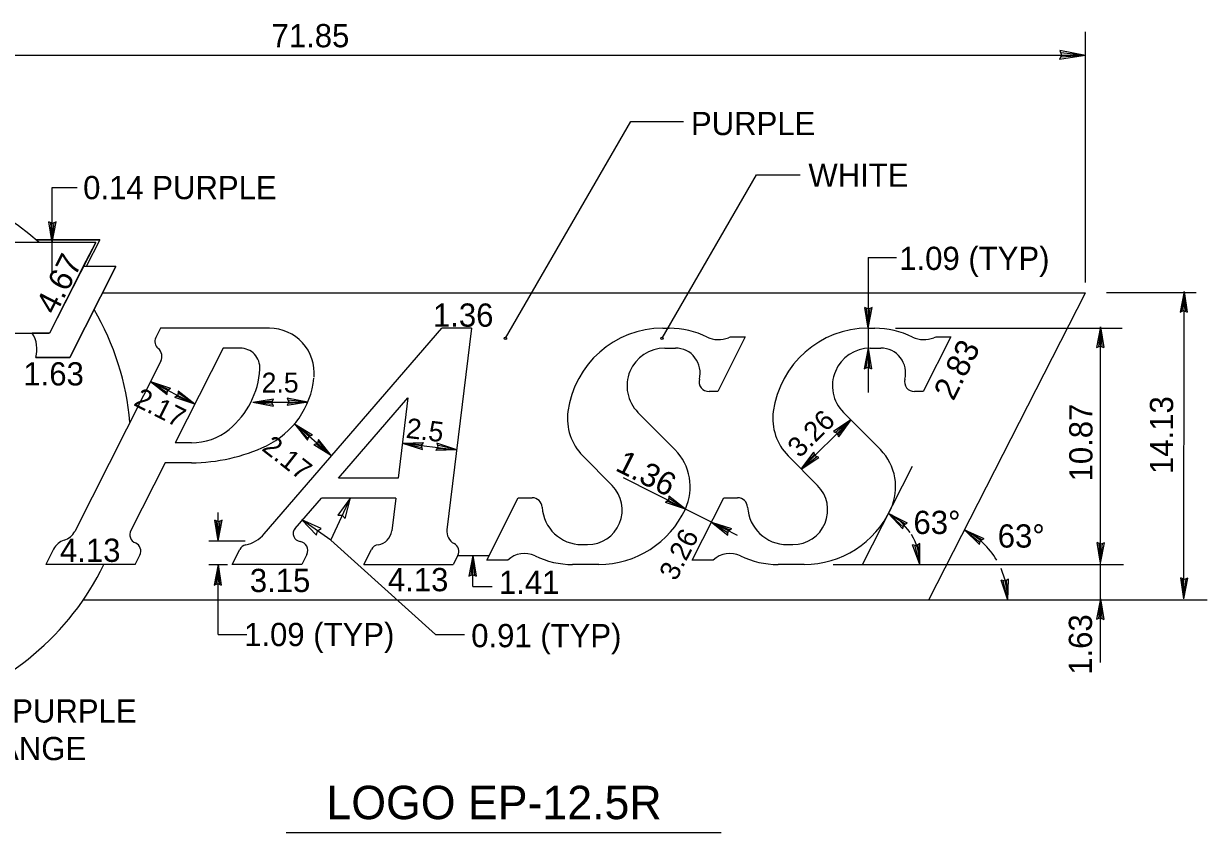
# Model space of a CAD drawing. Extents: x 10268197 to 10268826, y 2141503 to 2142677.
# Drawn here: x 10268696.97 to 10268727.52, y 2142400.42 to 2142421.3 of the extents above; entities that cross this region are included whole.
import ezdxf

# ---------------------------------------------------------------- set-up
doc = ezdxf.new("R2010")
doc.units = 0
doc.layers.add('Default', color=7, linetype='Continuous')
doc.layers.add('TextDetails', color=7, linetype='Continuous')

msp = doc.modelspace()

# ---------------------------------------------------------------- linework, layer by layer
at = {"layer": 'Default'}
for p, q in [((10268724.378, 2142414.961), (10268724.378, 2142421.09)), ((10268724.378, 2142420.48), (10268684.064, 2142420.48)), ((10268723.763, 2142420.49), (10268723.71, 2142420.374)), ((10268724.378, 2142420.48), (10268723.71, 2142420.374)), ((10268724.378, 2142420.48), (10268723.714, 2142420.609)), ((10268723.714, 2142420.609), (10268723.763, 2142420.49)), ((10268724.378, 2142420.48), (10268723.738, 2142420.435)), ((10268724.378, 2142420.48), (10268723.739, 2142420.547)), ((10268709.405, 2142413.178), (10268712.638, 2142418.777)), ((10268712.638, 2142418.777), (10268713.999, 2142418.777)), ((10268713.448, 2142413.178), (10268715.883, 2142417.397)), ((10268715.883, 2142417.397), (10268717.013, 2142417.397)), ((10268697.702, 2142415.718), (10268697.702, 2142417.074)), ((10268697.702, 2142417.074), (10268698.344, 2142417.074)), ((10268697.702, 2142415.653), (10268697.617, 2142416.188)), ((10268697.71, 2142416.145), (10268697.617, 2142416.188)), ((10268697.702, 2142415.653), (10268697.666, 2142416.165)), ((10268697.702, 2142415.653), (10268697.805, 2142416.184)), ((10268697.702, 2142415.653), (10268697.755, 2142416.164)), ((10268697.805, 2142416.184), (10268697.71, 2142416.145)), ((10268698.825, 2142415.653), (10268691.433, 2142415.653)), ((10268698.931, 2142415.719), (10268697.287, 2142415.719)), ((10268698.825, 2142415.653), (10268697.631, 2142413.31)), ((10268697.702, 2142414.831), (10268697.702, 2142415.653)), ((10268698.931, 2142415.719), (10268698.578, 2142415.027)), ((10268718.765, 2142415.262), (10268718.765, 2142413.436)), ((10268718.765, 2142415.262), (10268719.5, 2142415.262)), ((10268698.506, 2142415.027), (10268697.631, 2142413.31)), ((10268698.155, 2142412.683), (10268699.349, 2142415.027)), ((10268699.349, 2142415.027), (10268698.155, 2142412.683)), ((10268699.349, 2142415.027), (10268698.506, 2142415.027)), ((10268699.349, 2142415.027), (10268698.506, 2142415.027)), ((10268724.378, 2142414.614), (10268724.378, 2142414.961)), ((10268699.004, 2142414.351), (10268724.378, 2142414.351)), ((10268720.337, 2142406.419), (10268724.378, 2142414.351)), ((10268727.232, 2142414.351), (10268724.925, 2142414.351)), ((10268726.922, 2142414.384), (10268726.819, 2142413.853)), ((10268726.922, 2142414.384), (10268726.868, 2142413.874)), ((10268726.921, 2142406.452), (10268726.922, 2142414.384)), ((10268726.922, 2142414.384), (10268727.007, 2142413.85)), ((10268726.922, 2142414.384), (10268726.958, 2142413.873)), ((10268718.765, 2142413.436), (10268718.68, 2142413.971)), ((10268718.774, 2142413.929), (10268718.68, 2142413.971)), ((10268718.765, 2142413.436), (10268718.729, 2142413.948)), ((10268718.765, 2142413.436), (10268718.868, 2142413.968)), ((10268718.765, 2142413.436), (10268718.819, 2142413.947)), ((10268718.868, 2142413.968), (10268718.774, 2142413.929)), ((10268726.819, 2142413.853), (10268726.913, 2142413.892)), ((10268726.913, 2142413.892), (10268727.007, 2142413.85)), ((10268696.739, 2142413.309), (10268697.631, 2142413.31)), ((10268697.631, 2142413.31), (10268697.185, 2142413.31)), ((10268700.498, 2142413.436), (10268700.376, 2142413.195)), ((10268703.313, 2142413.436), (10268700.498, 2142413.436)), ((10268703.177, 2142408.127), (10268707.758, 2142413.436)), ((10268708.528, 2142413.436), (10268707.758, 2142413.436)), ((10268708.528, 2142413.436), (10268707.894, 2142408.233)), ((10268713.463, 2142413.436), (10268713.632, 2142413.436)), ((10268718.765, 2142413.436), (10268718.936, 2142413.436)), ((10268718.765, 2142413.436), (10268718.765, 2142412.922)), ((10268719.475, 2142413.436), (10268725.324, 2142413.436)), ((10268724.766, 2142413.469), (10268724.663, 2142412.938)), ((10268724.766, 2142413.469), (10268724.712, 2142412.959)), ((10268724.766, 2142407.367), (10268724.766, 2142413.469)), ((10268724.766, 2142413.469), (10268724.85, 2142412.935)), ((10268724.766, 2142413.469), (10268724.802, 2142412.957)), ((10268715.596, 2142413.211), (10268714.883, 2142411.801)), ((10268715.26, 2142413.211), (10268715.596, 2142413.211)), ((10268720.899, 2142413.211), (10268720.186, 2142411.801)), ((10268720.563, 2142413.211), (10268720.899, 2142413.211)), ((10268702.114, 2142412.923), (10268700.877, 2142410.475)), ((10268702.552, 2142412.923), (10268702.114, 2142412.923)), ((10268713.517, 2142412.923), (10268713.79, 2142412.923)), ((10268718.765, 2142412.922), (10268718.662, 2142412.391)), ((10268718.765, 2142412.922), (10268718.712, 2142412.411)), ((10268718.765, 2142412.922), (10268718.765, 2142411.78)), ((10268718.765, 2142412.922), (10268718.85, 2142412.387)), ((10268718.765, 2142412.922), (10268718.801, 2142412.41)), ((10268718.82, 2142412.923), (10268719.093, 2142412.923)), ((10268724.663, 2142412.938), (10268724.757, 2142412.977)), ((10268724.757, 2142412.977), (10268724.85, 2142412.935)), ((10268698.155, 2142412.683), (10268697.278, 2142412.683)), ((10268697.278, 2142412.683), (10268698.155, 2142412.683)), ((10268700.506, 2142412.582), (10268698.284, 2142408.19)), ((10268718.662, 2142412.391), (10268718.757, 2142412.43)), ((10268718.757, 2142412.43), (10268718.85, 2142412.387)), ((10268700.24, 2142412.057), (10268701.384, 2142411.478)), ((10268700.24, 2142412.057), (10268700.755, 2142411.891)), ((10268700.24, 2142412.057), (10268700.667, 2142411.725)), ((10268700.24, 2142412.057), (10268700.672, 2142411.779)), ((10268700.24, 2142412.057), (10268700.713, 2142411.858)), ((10268700.667, 2142411.725), (10268700.675, 2142411.827)), ((10268700.675, 2142411.827), (10268700.755, 2142411.891)), ((10268700.956, 2142411.81), (10268700.948, 2142411.708)), ((10268701.384, 2142411.478), (10268700.956, 2142411.81)), ((10268714.883, 2142411.801), (10268714.659, 2142411.801)), ((10268720.186, 2142411.801), (10268719.962, 2142411.801)), ((10268700.948, 2142411.708), (10268700.869, 2142411.644)), ((10268701.384, 2142411.478), (10268700.869, 2142411.644)), ((10268701.384, 2142411.478), (10268700.911, 2142411.678)), ((10268701.384, 2142411.478), (10268700.952, 2142411.756)), ((10268702.881, 2142411.53), (10268703.415, 2142411.615)), ((10268702.881, 2142411.53), (10268703.393, 2142411.566)), ((10268702.881, 2142411.53), (10268704.302, 2142411.53)), ((10268702.881, 2142411.53), (10268703.412, 2142411.427)), ((10268702.881, 2142411.53), (10268703.391, 2142411.477)), ((10268703.373, 2142411.521), (10268703.415, 2142411.615)), ((10268703.412, 2142411.427), (10268703.373, 2142411.521)), ((10268703.81, 2142411.538), (10268703.768, 2142411.445)), ((10268704.302, 2142411.53), (10268703.768, 2142411.445)), ((10268704.302, 2142411.53), (10268703.771, 2142411.633)), ((10268703.771, 2142411.633), (10268703.81, 2142411.538)), ((10268704.302, 2142411.53), (10268703.79, 2142411.494)), ((10268704.302, 2142411.53), (10268703.792, 2142411.583)), ((10268705.094, 2142409.564), (10268706.888, 2142411.643)), ((10268706.888, 2142411.643), (10268706.636, 2142409.564)), ((10268712.825, 2142411.263), (10268713.78, 2142410.301)), ((10268718.129, 2142411.263), (10268719.084, 2142410.301)), ((10268704.916, 2142410.142), (10268703.96, 2142410.967)), ((10268703.96, 2142410.967), (10268704.42, 2142410.682)), ((10268703.96, 2142410.967), (10268704.295, 2142410.542)), ((10268703.96, 2142410.967), (10268704.312, 2142410.593)), ((10268703.96, 2142410.967), (10268704.371, 2142410.659)), ((10268717.042, 2142409.8), (10268718.321, 2142411.07)), ((10268718.321, 2142411.07), (10268717.871, 2142410.769)), ((10268718.321, 2142411.07), (10268717.921, 2142410.748)), ((10268718.321, 2142411.07), (10268717.983, 2142410.684)), ((10268718.321, 2142411.07), (10268718.001, 2142410.633)), ((10268704.295, 2142410.542), (10268704.327, 2142410.639)), ((10268704.327, 2142410.639), (10268704.42, 2142410.682)), ((10268704.581, 2142410.567), (10268704.548, 2142410.47)), ((10268704.916, 2142410.142), (10268704.581, 2142410.567)), ((10268717.871, 2142410.769), (10268717.966, 2142410.729)), ((10268717.966, 2142410.729), (10268718.001, 2142410.633)), ((10268701.295, 2142410.476), (10268700.877, 2142410.475)), ((10268704.548, 2142410.47), (10268704.455, 2142410.427)), ((10268704.916, 2142410.142), (10268704.455, 2142410.427)), ((10268704.916, 2142410.142), (10268704.505, 2142410.449)), ((10268704.916, 2142410.142), (10268704.564, 2142410.516)), ((10268706.746, 2142410.47), (10268707.286, 2142410.489)), ((10268706.746, 2142410.47), (10268708.145, 2142410.3)), ((10268706.746, 2142410.47), (10268707.26, 2142410.303)), ((10268706.746, 2142410.47), (10268707.246, 2142410.355)), ((10268706.746, 2142410.47), (10268707.258, 2142410.444)), ((10268707.233, 2142410.402), (10268707.286, 2142410.489)), ((10268707.26, 2142410.303), (10268707.233, 2142410.402)), ((10268707.657, 2142410.367), (10268707.604, 2142410.28)), ((10268708.145, 2142410.3), (10268707.604, 2142410.28)), ((10268708.145, 2142410.3), (10268707.63, 2142410.466)), ((10268707.63, 2142410.466), (10268707.657, 2142410.367)), ((10268708.145, 2142410.3), (10268707.632, 2142410.326)), ((10268708.145, 2142410.3), (10268707.644, 2142410.414)), ((10268700.617, 2142409.963), (10268699.732, 2142408.211)), ((10268701.295, 2142409.963), (10268700.617, 2142409.963)), ((10268712.159, 2142409.377), (10268711.399, 2142410.143)), ((10268717.462, 2142409.377), (10268716.702, 2142410.143)), ((10268717.042, 2142409.8), (10268717.362, 2142410.237)), ((10268717.042, 2142409.8), (10268717.38, 2142410.186)), ((10268717.042, 2142409.8), (10268717.442, 2142410.122)), ((10268717.042, 2142409.8), (10268717.491, 2142410.101)), ((10268717.397, 2142410.141), (10268717.362, 2142410.237)), ((10268717.491, 2142410.101), (10268717.397, 2142410.141)), ((10268718.62, 2142407.334), (10268719.913, 2142409.872)), ((10268706.636, 2142409.564), (10268705.094, 2142409.564)), ((10268714.048, 2142408.768), (10268712.454, 2142409.573)), ((10268703.974, 2142408.266), (10268704.652, 2142409.052)), ((10268706.573, 2142409.052), (10268704.652, 2142409.052)), ((10268704.892, 2142407.965), (10268705.403, 2142409.059)), ((10268705.403, 2142409.059), (10268705.079, 2142408.613)), ((10268705.265, 2142408.526), (10268705.403, 2142409.059)), ((10268706.573, 2142409.052), (10268706.47, 2142408.202)), ((10268708.921, 2142407.447), (10268709.736, 2142409.059)), ((10268709.736, 2142409.059), (10268710.096, 2142409.059)), ((10268713.62, 2142409.099), (10268713.612, 2142408.997)), ((10268714.048, 2142408.768), (10268713.616, 2142409.046)), ((10268714.048, 2142408.768), (10268713.62, 2142409.099)), ((10268714.225, 2142407.447), (10268715.039, 2142409.059)), ((10268715.039, 2142409.059), (10268715.399, 2142409.058)), ((10268713.612, 2142408.997), (10268713.532, 2142408.933)), ((10268714.048, 2142408.768), (10268713.532, 2142408.933)), ((10268714.048, 2142408.768), (10268713.575, 2142408.967)), ((10268714.721, 2142408.427), (10268714.048, 2142408.768)), ((10268701.984, 2142407.944), (10268701.899, 2142408.479)), ((10268701.993, 2142408.437), (10268701.899, 2142408.479)), ((10268701.984, 2142407.944), (10268701.948, 2142408.456)), ((10268701.984, 2142407.944), (10268701.984, 2142408.68)), ((10268701.984, 2142407.944), (10268702.087, 2142408.476)), ((10268701.984, 2142407.944), (10268702.037, 2142408.455)), ((10268702.087, 2142408.476), (10268701.993, 2142408.437)), ((10268704.892, 2142407.965), (10268704.147, 2142408.493)), ((10268704.147, 2142408.493), (10268704.528, 2142408.095)), ((10268704.646, 2142408.262), (10268704.147, 2142408.493)), ((10268705.079, 2142408.613), (10268705.191, 2142408.606)), ((10268705.191, 2142408.606), (10268705.265, 2142408.526)), ((10268715.393, 2142408.087), (10268714.72, 2142408.427)), ((10268714.72, 2142408.427), (10268715.236, 2142408.262)), ((10268714.72, 2142408.427), (10268715.148, 2142408.096)), ((10268714.72, 2142408.427), (10268715.152, 2142408.149)), ((10268714.72, 2142408.427), (10268715.193, 2142408.228)), ((10268719.293, 2142408.656), (10268719.775, 2142408.409)), ((10268719.293, 2142408.656), (10268719.661, 2142408.259)), ((10268719.293, 2142408.656), (10268719.674, 2142408.312)), ((10268719.293, 2142408.656), (10268719.727, 2142408.383)), ((10268719.685, 2142408.359), (10268719.775, 2142408.409)), ((10268704.528, 2142408.095), (10268704.555, 2142408.204)), ((10268704.555, 2142408.204), (10268704.646, 2142408.262)), ((10268715.148, 2142408.096), (10268715.156, 2142408.198)), ((10268715.156, 2142408.198), (10268715.236, 2142408.262)), ((10268719.661, 2142408.259), (10268719.685, 2142408.359)), ((10268721.259, 2142408.23), (10268721.752, 2142408.005)), ((10268721.259, 2142408.23), (10268721.645, 2142407.85)), ((10268721.259, 2142408.23), (10268721.656, 2142407.903)), ((10268721.259, 2142408.23), (10268721.706, 2142407.977)), ((10268701.743, 2142407.944), (10268702.683, 2142407.944)), ((10268707.597, 2142405.525), (10268704.892, 2142407.965)), ((10268711.523, 2142407.847), (10268711.376, 2142407.847)), ((10268716.826, 2142407.847), (10268716.679, 2142407.847)), ((10268720.104, 2142407.336), (10268719.916, 2142407.844)), ((10268720.016, 2142407.82), (10268719.916, 2142407.844)), ((10268720.104, 2142407.336), (10268719.969, 2142407.831)), ((10268720.102, 2142407.877), (10268720.016, 2142407.82)), ((10268720.104, 2142407.336), (10268720.057, 2142407.847)), ((10268720.104, 2142407.336), (10268720.102, 2142407.877)), ((10268721.645, 2142407.85), (10268721.665, 2142407.951)), ((10268721.665, 2142407.951), (10268721.752, 2142408.005)), ((10268724.766, 2142407.367), (10268724.681, 2142407.902)), ((10268724.774, 2142407.859), (10268724.681, 2142407.902)), ((10268724.766, 2142407.367), (10268724.73, 2142407.879)), ((10268724.766, 2142407.367), (10268724.869, 2142407.898)), ((10268724.766, 2142407.367), (10268724.819, 2142407.878)), ((10268724.869, 2142407.898), (10268724.774, 2142407.859)), ((10268697.739, 2142407.733), (10268697.538, 2142407.334)), ((10268699.845, 2142407.334), (10268699.966, 2142407.576)), ((10268702.352, 2142407.334), (10268702.547, 2142407.721)), ((10268704.279, 2142407.596), (10268704.146, 2142407.334)), ((10268705.75, 2142407.334), (10268705.946, 2142407.721)), ((10268708.174, 2142407.567), (10268708.057, 2142407.334)), ((10268708.174, 2142407.567), (10268708.982, 2142407.568)), ((10268708.565, 2142407.567), (10268708.462, 2142407.036)), ((10268708.565, 2142407.567), (10268708.512, 2142407.057)), ((10268708.565, 2142406.771), (10268708.565, 2142407.567)), ((10268708.565, 2142407.567), (10268708.65, 2142407.033)), ((10268708.565, 2142407.567), (10268708.601, 2142407.055)), ((10268699.845, 2142407.334), (10268697.538, 2142407.334)), ((10268701.743, 2142407.334), (10268702.225, 2142407.334)), ((10268701.984, 2142407.334), (10268701.881, 2142406.803)), ((10268701.984, 2142407.334), (10268701.931, 2142406.823)), ((10268701.984, 2142405.525), (10268701.984, 2142407.334)), ((10268701.984, 2142407.334), (10268702.069, 2142406.8)), ((10268701.984, 2142407.334), (10268702.02, 2142406.822)), ((10268704.146, 2142407.334), (10268702.352, 2142407.334)), ((10268705.75, 2142407.334), (10268708.057, 2142407.334)), ((10268709.466, 2142407.447), (10268708.921, 2142407.447)), ((10268711.813, 2142407.334), (10268711.138, 2142407.334)), ((10268714.769, 2142407.447), (10268714.225, 2142407.447)), ((10268717.116, 2142407.334), (10268716.441, 2142407.334)), ((10268717.863, 2142407.334), (10268720.803, 2142407.334)), ((10268720.803, 2142407.334), (10268725.357, 2142407.334)), ((10268724.766, 2142406.452), (10268724.766, 2142407.367)), ((10268708.462, 2142407.036), (10268708.557, 2142407.075)), ((10268708.557, 2142407.075), (10268708.65, 2142407.033)), ((10268722.37, 2142406.417), (10268722.203, 2142406.932)), ((10268722.301, 2142406.904), (10268722.203, 2142406.932)), ((10268722.37, 2142406.417), (10268722.255, 2142406.917)), ((10268722.389, 2142406.958), (10268722.301, 2142406.904)), ((10268722.37, 2142406.417), (10268722.343, 2142406.93)), ((10268722.37, 2142406.417), (10268722.389, 2142406.958)), ((10268726.921, 2142406.452), (10268726.837, 2142406.987)), ((10268726.93, 2142406.944), (10268726.837, 2142406.987)), ((10268726.921, 2142406.452), (10268726.885, 2142406.964)), ((10268726.921, 2142406.452), (10268727.025, 2142406.983)), ((10268726.921, 2142406.452), (10268726.975, 2142406.963)), ((10268727.025, 2142406.983), (10268726.93, 2142406.944)), ((10268701.881, 2142406.803), (10268701.976, 2142406.842)), ((10268701.976, 2142406.842), (10268702.069, 2142406.8)), ((10268708.565, 2142406.771), (10268709.065, 2142406.771)), ((10268698.505, 2142406.419), (10268720.337, 2142406.419)), ((10268720.337, 2142406.419), (10268727.524, 2142406.419)), ((10268724.766, 2142406.452), (10268724.662, 2142405.921)), ((10268724.766, 2142406.452), (10268724.712, 2142405.942)), ((10268724.766, 2142404.801), (10268724.766, 2142406.452)), ((10268724.766, 2142406.452), (10268724.85, 2142405.918)), ((10268724.766, 2142406.452), (10268724.801, 2142405.941)), ((10268724.662, 2142405.921), (10268724.757, 2142405.96)), ((10268724.757, 2142405.96), (10268724.85, 2142405.918)), ((10268701.984, 2142405.525), (10268702.731, 2142405.525)), ((10268707.597, 2142405.525), (10268708.344, 2142405.525))]:
    msp.add_line(p, q, dxfattribs=at)
msp.add_lwpolyline([(10268697.287, 2142415.719), (10268698.931, 2142415.719), (10268698.578, 2142415.027), (10268698.506, 2142415.027), (10268698.825, 2142415.653), (10268697.362, 2142415.654)], close=True, dxfattribs=at)
for centre in [(10268709.405, 2142413.178), (10268713.448, 2142413.178)]:
    msp.add_circle(centre, 0.0305, dxfattribs=at)
for centre, radius, start, end in [((10268692.721, 2142410.391), 7.017, 48.5904, 218.8792), ((10268692.721, 2142410.391), 7.017, 5.051, 30.1953), ((10268696.557, 2142412.897), 0.752, 343.4611, 33.2756), ((10268696.557, 2142412.897), 0.752, 343.4611, 33.2756), ((10268703.313, 2142412.283), 1.154, 354.6609, 90), ((10268702.552, 2142412.411), 0.513, 356.6133, 90), ((10268713.517, 2142411.949), 0.974, 90, 224.7881), ((10268713.79, 2142412.283), 0.641, 345.4379, 90), ((10268718.82, 2142411.949), 0.974, 90, 224.7881), ((10268719.093, 2142412.283), 0.641, 345.4379, 90), ((10268700.888, 2142412.509), 2.179, 309.3947, 356.6133), ((10268702.291, 2142412.368), 2.179, 295.579, 354.2619), ((10268714.659, 2142412.057), 0.256, 165.4379, 270), ((10268719.962, 2142412.057), 0.256, 165.4379, 270), ((10268701.295, 2142412.014), 1.538, 270, 309.3947), ((10268701.295, 2142414.449), 4.486, 270, 295.579), ((10268711.523, 2142408.745), 0.897, 270, 44.7784), ((10268716.826, 2142408.745), 0.897, 270, 44.7784), ((10268710.096, 2142408.802), 0.256, 3.1643, 90), ((10268715.399, 2142408.802), 0.256, 3.1643, 90), ((10268711.376, 2142408.873), 1.025, 183.1643, 270), ((10268716.679, 2142408.873), 1.025, 183.1643, 270), ((10268718.62, 2142407.334), 1.483, 33.9529, 63.0014), ((10268699.937, 2142408.107), 0.231, 153.1708, 247.5682), ((10268704.129, 2142408.132), 0.205, 139.1995, 262.5416), ((10268706.062, 2142408.252), 0.41, 277.9506, 353.082), ((10268708.25, 2142408.189), 0.359, 173.0593, 241.464), ((10268718.62, 2142407.334), 1.483, 0, 31.4593), ((10268720.336, 2142406.419), 2.031, 30.3328, 63.0012), ((10268699.761, 2142407.68), 0.231, 333.1431, 67.5682), ((10268704.072, 2142407.7), 0.231, 333.166, 82.5416), ((10268706.151, 2142407.617), 0.231, 97.9506, 153.1923), ((10268707.968, 2142407.671), 0.231, 333.284, 61.464), ((10268692.721, 2142410.391), 7.017, 237.0648, 334.1734), ((10268720.336, 2142406.419), 2.031, 360, 23.4794)]:
    msp.add_arc(centre, radius, start, end, dxfattribs=at)
for centre, major_axis, start_param, end_param in [((10268713.462, 2142410.95), (0, 2.486), 0, 1.436562), ((10268713.632, 2142411.176), (0, 2.26), 5.830963, 6.283185), ((10268718.765, 2142410.95), (0, 2.486), 0, 1.436562), ((10268718.935, 2142411.176), (0, 2.26), 5.830963, 6.283185), ((10268700.576, 2142413.092), (0, -0.226), 4.240773, 5.605302), ((10268714.906, 2142413.819), (0, 0.678), 2.68937, 3.526171), ((10268715.26, 2142412.939), (0, 0.271), 0, 0.384579), ((10268720.209, 2142413.819), (0, 0.678), 2.68937, 3.526171), ((10268720.563, 2142412.939), (0, 0.271), 0, 0.384579), ((10268700.266, 2142412.705), (0, -0.271), 1.099604, 2.46371), ((10268712.35, 2142411.102), (0, 1.356), 1.436562, 2.356194), ((10268717.653, 2142411.102), (0, 1.356), 1.436562, 2.356194), ((10268712.829, 2142409.342), (0, -1.356), 1.133591, 2.356194), ((10268718.132, 2142409.342), (0, -1.356), 1.133591, 2.356194), ((10268711.813, 2142409.821), (0, -2.486), 0, 1.133591), ((10268717.116, 2142409.821), (0, -2.486), 0, 1.133591), ((10268697.885, 2142408.395), (0, -0.452), 0.286787, 1.099486), ((10268702.5, 2142408.721), (0, -0.904), 0.22194, 0.855152), ((10268698.139, 2142407.528), (0, -0.452), 3.428379, 4.240701), ((10268702.747, 2142407.619), (0, -0.226), 3.363532, 4.241567), ((10268709.896, 2142406.986), (0, -0.633), 2.69443, 3.895387), ((10268711.138, 2142409.595), (0, -2.26), 5.836023, 6.283185), ((10268715.199, 2142406.986), (0, -0.633), 2.69443, 3.895387), ((10268716.441, 2142409.595), (0, -2.26), 5.836023, 6.283185)]:
    msp.add_ellipse(centre, major_axis=major_axis, ratio=0.992614, start_param=start_param, end_param=end_param, dxfattribs=at)
at = {"layer": 'TextDetails'}
msp.add_line((10268703.739, 2142400.419), (10268714.969, 2142400.419), dxfattribs=at)

# ---------------------------------------------------------------- texts
at = {"layer": 'Default'}
for s, height, p in [('71.85', 0.5999, (10268703.366, 2142420.692)), ('PURPLE', 0.5999, (10268714.194, 2142418.424)), ('WHITE', 0.5999, (10268717.225, 2142417.088)), ('0.14 PURPLE', 0.59994, (10268698.502, 2142416.769)), ('1.09 (TYP)', 0.5999, (10268719.571, 2142414.941)), ('1.36', 0.5999, (10268707.533, 2142413.476)), ('1.63', 0.5999, (10268696.958, 2142411.959)), ('2.5', 0.5142, (10268703.109, 2142411.775)), ('63°', 0.5999, (10268719.938, 2142408.123)), ('63°', 0.5999, (10268722.113, 2142407.772)), ('4.13', 0.5999, (10268697.904, 2142407.403)), ('3.15', 0.5999, (10268702.805, 2142406.624)), ('4.13', 0.5999, (10268706.369, 2142406.645)), ('1.41', 0.5999, (10268709.235, 2142406.577)), ('1.09 (TYP)', 0.5999, (10268702.658, 2142405.229)), ('0.91 (TYP)', 0.5999, (10268708.52, 2142405.199)), ('PURPLE', 0.5999, (10268696.671, 2142403.254)), ('ORANGE', 0.5999, (10268695.103, 2142402.283))]:
    msp.add_text(s, height=height, dxfattribs=at).set_placement(p)
for s, height, rotation, p in [('4.67', 0.5999, 63.001, (10268697.787, 2142413.759)), ('2.83', 0.5999, 63.1678, (10268720.968, 2142411.539)), ('2.17', 0.5142, 333.1665, (10268699.778, 2142411.458)), ('14.13', 0.5999, 90, (10268726.641, 2142409.674)), ('3.26', 0.5142, 44.7737, (10268716.999, 2142410.067)), ('10.87', 0.5999, 90, (10268724.559, 2142409.481)), ('2.5', 0.5174, 353.0765, (10268706.819, 2142410.608)), ('2.17', 0.5142, 321.8741, (10268703.089, 2142410.301)), ('1.36', 0.5999, 333.1861, (10268712.214, 2142409.778)), ('3.26', 0.5142, 63.1839, (10268713.807, 2142406.886)), ('1.63', 0.5999, 90, (10268724.547, 2142404.488))]:
    msp.add_text(s, height=height, rotation=rotation, dxfattribs=at).set_placement(p)
at = {"layer": 'TextDetails'}
msp.add_text('LOGO EP-12.5R', height=0.8624, dxfattribs=at).set_placement((10268704.783, 2142400.759))

doc.saveas('drawing.dxf')
